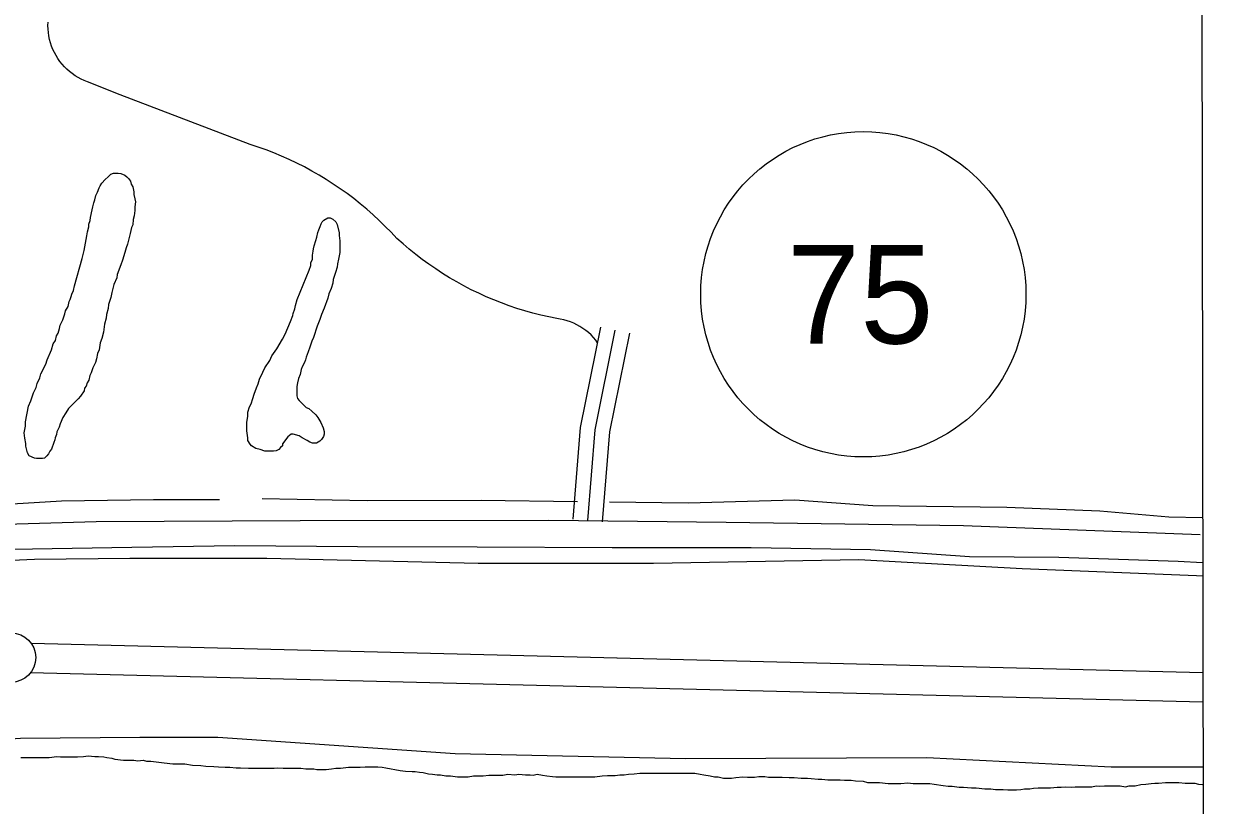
# Model space of a CAD drawing. Extents: x 3297772 to 3335630, y 634068 to 659439.
# Drawn here: x 3332239 to 3333452, y 650673 to 651465 of the extents above; entities that cross this region are included whole.
import ezdxf

# ---------------------------------------------------------------- set-up
doc = ezdxf.new("R2010")
doc.units = 0
for name, color, linetype in [('V-GRID-FRAM', 7, 'Continuous'), ('V-LEVE-TOET', 7, 'Continuous'), ('V-ROAD-CNTR', 7, 'Continuous'), ('V-ROAD-IDEN', 7, 'Continuous'), ('V-SITE-VEGE', 7, 'Continuous'), ('V-SURV-LINE', 7, 'Continuous'), ('V-TOPO-SHOR', 7, 'Continuous')]:
    doc.layers.add(name, color=color, linetype=linetype)

msp = doc.modelspace()

# ---------------------------------------------------------------- linework, layer by layer
at = {"layer": 'V-GRID-FRAM'}
msp.add_lwpolyline([(3301870.2, 657630.6), (3333425.5, 657662.7), (3333452, 639478.7), (3301880.8, 639446.5), (3301870.2, 657630.6)], dxfattribs=at)
at = {"layer": 'V-LEVE-TOET'}
for points in [[(3329935.1, 650681.5), (3330160.7, 650698.7), (3330335.6, 650710.8), (3330546, 650738.2), (3330678.2, 650757.4), (3330832.7, 650781.8), (3330990.3, 650805.1), (3331122.4, 650823.4), (3331283, 650842.6), (3331453.8, 650854.8), (3331601.2, 650866.9), (3331733.4, 650883.1), (3331859.4, 650896.3), (3331986.5, 650908.4), (3332089.2, 650915.5), (3332249.8, 650922.6), (3332346.4, 650923.6), (3332485.6, 650923.5), (3332700.1, 650918.3), (3332878, 650918.3), (3333086.4, 650922.3), (3333252.1, 650913.1), (3333429, 650905.9), (3333435.4, 650905.5)], [(3333435.6, 650711.6), (3333434, 650711.7), (3333342.5, 650711.7), (3333155.5, 650721), (3332910.5, 650720), (3332676.7, 650725.2), (3332435.8, 650741.6), (3332356.5, 650741.6), (3332235.5, 650740.6), (3332099.3, 650731.5), (3331851.2, 650711.3), (3331608.3, 650690), (3331357.2, 650671.8), (3331163, 650652.6), (3331004.4, 650628.2), (3330896.7, 650612), (3330716.7, 650578.5), (3330574.4, 650555.2), (3330476.8, 650542), (3330268.4, 650518.7), (3330075.3, 650499.5), (3329982.8, 650488.3)]]:
    msp.add_lwpolyline(points, dxfattribs=at)
at = {"layer": 'V-ROAD-CNTR'}
for points in [[(3332288, 651415), (3332285.2, 651417.2), (3332282.6, 651419.5), (3332280.1, 651422), (3332277.7, 651424.6), (3332275.5, 651427.4), (3332273.5, 651430.3), (3332271.6, 651433.3), (3332269.9, 651436.4), (3332268.4, 651439.6), (3332267.1, 651442.9), (3332266, 651446.3), (3332265.1, 651449.7), (3332264.4, 651453.2), (3332263.8, 651456.7), (3332263.5, 651460.2), (3332263.4, 651463.7), (3332263.5, 651467.3)], [(3332656.9, 651216.9), (3332650, 651221.6), (3332643.3, 651226.5), (3332636.6, 651231.6), (3332630.1, 651236.9), (3332623.8, 651242.3), (3332617.5, 651247.8), (3332611.7, 651254.1), (3332605.7, 651260.1), (3332599.6, 651266.1), (3332593.4, 651271.8), (3332586.9, 651277.4), (3332580.4, 651282.9), (3332573.7, 651288.2), (3332566.9, 651293.3), (3332560, 651298.2), (3332552.9, 651303), (3332545.8, 651307.6), (3332538.5, 651312), (3332531.1, 651316.2), (3332523.6, 651320.3), (3332516, 651324.1), (3332508.3, 651327.8), (3332500.5, 651331.3), (3332492.7, 651334.6), (3332484.7, 651337.6), (3332476.7, 651340.5), (3332468.7, 651343.2), (3332336.6, 651393.6), (3332303.5, 651406.6), (3332300.2, 651407.9), (3332297, 651409.4), (3332293.9, 651411.1), (3332290.9, 651412.9), (3332288, 651415)], [(3332821.2, 651142.1), (3332819.3, 651144.6), (3332817, 651147.3), (3332814.6, 651149.9), (3332812, 651152.3), (3332809.2, 651154.5), (3332806.3, 651156.6), (3332803.3, 651158.6), (3332800.2, 651160.3), (3332797, 651161.8), (3332793.7, 651163.2), (3332790.4, 651164.3), (3332786.9, 651165.3), (3332783.4, 651166), (3332779.9, 651166.6), (3332771.7, 651168.2), (3332763.6, 651170.1), (3332755.5, 651172.1), (3332747.4, 651174.4), (3332739.4, 651176.9), (3332731.5, 651179.5), (3332723.7, 651182.4), (3332715.9, 651185.5), (3332708.2, 651188.7), (3332700.6, 651192.2), (3332693, 651195.8), (3332685.6, 651199.7), (3332678.3, 651203.7), (3332671, 651207.9), (3332663.9, 651212.3), (3332656.9, 651216.9)], [(3332796.3, 650963), (3332804, 651055.9), (3332824.4, 651157.7)], [(3332811.2, 650961.7), (3332818.9, 651053.8), (3332839.1, 651154.7)], [(3332826.1, 650960.5), (3332833.8, 651051.7), (3332853.8, 651151.8)], [(3329966, 650728.3), (3330358.9, 650756.1), (3330604, 650788.3), (3330853.6, 650826.4), (3331016.6, 650849.1), (3331146.5, 650864.5), (3331250.8, 650874), (3331392.6, 650887.9), (3331650.9, 650915.1), (3331869.6, 650937.5), (3332004, 650949.5), (3332127.9, 650955.3), (3332312.3, 650960.6), (3332519.4, 650961.7), (3332771.6, 650962.2), (3332951.8, 650960.2), (3333192.7, 650956.6), (3333432.9, 650947.5)]]:
    msp.add_lwpolyline(points, dxfattribs=at)
at = {"layer": 'V-ROAD-IDEN'}
msp.add_circle((3333090.9, 651191.2), 165, dxfattribs=at)
at = {"layer": 'V-SITE-VEGE'}
for points in [[(3332245.9, 651083), (3332248.6, 651091.1), (3332251.4, 651096.5), (3332252.4, 651100.8), (3332255.1, 651106.3), (3332256.2, 651110.6), (3332261.1, 651120.3), (3332262.7, 651124.7), (3332267.1, 651134.9), (3332268.7, 651140.9), (3332270.9, 651144.2), (3332271.9, 651149), (3332273.6, 651151.7), (3332275.2, 651156.6), (3332275.7, 651159.8), (3332278.5, 651165.3), (3332280.6, 651171.2), (3332281.2, 651174.5), (3332283.9, 651178.8), (3332285, 651183.7), (3332286, 651185.8), (3332287.1, 651189.1), (3332287.7, 651191.2), (3332289.3, 651195), (3332290.4, 651199.9), (3332298, 651227.5), (3332300.1, 651235.6), (3332302.8, 651250.3), (3332303.4, 651254.6), (3332305, 651259.5), (3332305, 651262.2), (3332306.1, 651266), (3332306.6, 651269.2), (3332308.3, 651276.8), (3332308.8, 651280), (3332309.9, 651283.8), (3332311, 651287.1), (3332312.1, 651291.4), (3332313.7, 651294.7), (3332315.3, 651299), (3332316.4, 651301.2), (3332318, 651303.9), (3332321.3, 651307.7), (3332324.5, 651310.4), (3332327.2, 651313.1), (3332329.9, 651314.1), (3332334.8, 651314.1), (3332337.5, 651313.6), (3332341.3, 651312), (3332343.5, 651310.4), (3332345.1, 651308.7), (3332347.3, 651306), (3332347.8, 651302.8), (3332349.4, 651300.1), (3332350.5, 651295.2), (3332350.5, 651292.5), (3332351.6, 651288.1), (3332352.1, 651284.9), (3332351.6, 651280), (3332351.6, 651276.2), (3332351, 651270.8), (3332350, 651267), (3332349.4, 651261.6), (3332348.3, 651258.9), (3332346.7, 651253), (3332344, 651242.1), (3332342.9, 651238.3), (3332341.3, 651233.5), (3332339.1, 651225.9), (3332337.5, 651221), (3332333.7, 651211.3), (3332333.2, 651208), (3332330.4, 651201), (3332328.3, 651192.9), (3332327.2, 651188), (3332325, 651180.9), (3332324.5, 651176.6), (3332322.9, 651170.7), (3332322.3, 651166.9), (3332320.7, 651160.9), (3332319.6, 651152.8), (3332318, 651146.3), (3332316.3, 651142), (3332315.3, 651134.9), (3332313.6, 651131.1), (3332312.5, 651125.7), (3332311.5, 651121.9), (3332308.8, 651116.5), (3332307.1, 651111.6), (3332306, 651108.9), (3332305, 651104.1), (3332303.3, 651101.4), (3332302.2, 651098.1), (3332300.6, 651095.9), (3332300.1, 651093.2), (3332296.3, 651087.8), (3332294.1, 651085.1), (3332284.4, 651075.4), (3332281.7, 651071), (3332278.4, 651066.2), (3332275.7, 651059.7)], [(3332481.5, 651112.1), (3332483.6, 651116.5), (3332488.5, 651124), (3332490.7, 651128.9), (3332495.6, 651135.9), (3332501.5, 651145.7), (3332504.2, 651150.6), (3332509.7, 651163.6), (3332511.8, 651169.5), (3332512.4, 651171.7), (3332514, 651176.5), (3332514.5, 651179.8), (3332516.2, 651185.8), (3332528.6, 651215.5), (3332530.3, 651220.4), (3332530.3, 651223.1), (3332531.9, 651226.9), (3332531.9, 651230.7), (3332532.4, 651235), (3332533, 651237.2), (3332533.5, 651240.4), (3332535.1, 651245.8), (3332536.2, 651249.1), (3332537.3, 651254), (3332538.4, 651256.7), (3332539.5, 651259.9), (3332540.6, 651262.6), (3332541.6, 651264.8), (3332543.3, 651266.4), (3332547.6, 651268.6), (3332549.8, 651268.6), (3332552.5, 651267.5), (3332555.7, 651264.8), (3332556.8, 651262.1), (3332559, 651253.4), (3332559, 651250.7), (3332559.5, 651245.3), (3332559.5, 651233.4), (3332558.4, 651226.9), (3332557.3, 651222), (3332556.8, 651218.8), (3332555.2, 651213.4), (3332554.1, 651210.1), (3332553, 651206.3), (3332552.4, 651202.5), (3332550.8, 651197.1), (3332548.6, 651191.7), (3332547.6, 651187.4), (3332543.8, 651177.1), (3332541.1, 651170.6), (3332539.4, 651165.7), (3332536.7, 651158.7), (3332532.9, 651147.3), (3332531.3, 651143.5), (3332529.1, 651137.6), (3332527.5, 651132.7), (3332525.3, 651127.3), (3332524.8, 651124.6), (3332523.7, 651121.9), (3332521.5, 651117.5), (3332520.5, 651114.8), (3332519.4, 651109.9), (3332517.8, 651105.6), (3332516.7, 651101.3), (3332516.1, 651097.5), (3332516.1, 651088.3), (3332516.7, 651085.6), (3332518.3, 651083.4), (3332525.3, 651076.4), (3332528, 651075.3), (3332531.3, 651072.6), (3332535.1, 651068.8), (3332537.2, 651066.1), (3332540.5, 651061.2), (3332542.6, 651055.8), (3332543.7, 651052), (3332543.7, 651049.3), (3332543.2, 651047.1), (3332541, 651043.9), (3332539.4, 651042.3), (3332536.1, 651040.1), (3332531.8, 651040.1), (3332529.1, 651041.2), (3332526.4, 651042.8), (3332521.5, 651045.5), (3332518.3, 651047.7), (3332512.3, 651049.3), (3332510.2, 651049.3), (3332506.9, 651046.6), (3332501.5, 651039.6), (3332501.5, 651037.4), (3332499.3, 651035.8), (3332497.7, 651033.6), (3332495, 651032.5), (3332492.3, 651032), (3332483.6, 651032), (3332478.7, 651033.6), (3332474.4, 651034.7), (3332470.1, 651037.4), (3332468.5, 651039), (3332466.3, 651042.8)], [(3332466.3, 651042.8), (3332466.3, 651045.5), (3332465.2, 651052.6), (3332465.2, 651061.2), (3332466.3, 651067.7), (3332466.3, 651071.5), (3332467.9, 651076.9), (3332469.6, 651080.2), (3332471.2, 651085.6), (3332472.8, 651089.9), (3332475, 651096.4), (3332476.6, 651100.2), (3332478.2, 651105.1), (3332481.5, 651112.1)], [(3332275.7, 651059.7), (3332274.6, 651056.4), (3332272.5, 651051.6), (3332271.9, 651048.9), (3332270.8, 651045.6), (3332270.3, 651043.4), (3332269.2, 651040.7), (3332267, 651034.2), (3332265.4, 651032.1), (3332263.8, 651029.4), (3332262.2, 651027.2), (3332260, 651025), (3332257.8, 651024.5), (3332251.9, 651024.5), (3332249.7, 651025), (3332244.3, 651027.2), (3332242.7, 651030.5), (3332242.1, 651033.2), (3332241, 651037), (3332241, 651039.7), (3332240, 651045.1), (3332239.4, 651050.5), (3332240.5, 651057.5), (3332240.5, 651061.9), (3332243.8, 651077.6), (3332245.9, 651083)]]:
    msp.add_lwpolyline(points, dxfattribs=at)
at = {"layer": 'V-SURV-LINE'}
for points in [[(3332246.3, 650837.2), (3333435.5, 650807.6)], [(3333435.6, 650777.6), (3332245.5, 650807.2)]]:
    msp.add_lwpolyline(points, dxfattribs=at)
msp.add_circle((3332226, 650822.7), 25, dxfattribs=at)
at = {"layer": 'V-TOPO-SHOR'}
for points in [[(3331720.3, 650940.1), (3331812.4, 650948), (3331897.3, 650958.6), (3331993.5, 650966.5), (3332078.7, 650974.7), (3332176.5, 650975.7), (3332277.3, 650981.6), (3332370.4, 650982.9), (3332437.4, 650983.2)], [(3332480.8, 650983.9), (3332587.3, 650981.9), (3332703, 650982.5), (3332800.8, 650981.1)], [(3332833.3, 650980.8), (3332913.2, 650979.7), (3333021.3, 650982.7), (3333100.5, 650977), (3333236.4, 650975.3), (3333330.9, 650971.6), (3333400.9, 650965.6), (3333435.3, 650964.7)], [(3331480.9, 650872.2), (3331601, 650879.7), (3331700.5, 650892.4), (3331786.7, 650899.9), (3331872, 650908.7), (3331934.8, 650912.7), (3332028.9, 650923.3), (3332129.3, 650927.2), (3332227.4, 650932.5), (3332348.6, 650934.6), (3332452.9, 650936.4), (3332577.5, 650935.4), (3332699.1, 650935), (3332836.1, 650934.5), (3332977.2, 650934.4), (3333098.3, 650932.2), (3333198.6, 650925.1), (3333289.2, 650924.6), (3333410.4, 650920.6), (3333435.3, 650919)], [(3332236, 650721.3), (3332240.8, 650721.3), (3332244.6, 650721.3), (3332250.1, 650721.3), (3332255.5, 650721.3), (3332259.3, 650721.3), (3332264.7, 650721.3), (3332272.3, 650722.4), (3332276.1, 650721.9), (3332282.6, 650721.9), (3332286.4, 650721.9), (3332293.4, 650721.9), (3332299.4, 650722.4), (3332304.3, 650722.9), (3332310.8, 650722.4), (3332314.6, 650722.4), (3332320, 650721.9), (3332323.3, 650721.3), (3332328.2, 650720.8), (3332331.4, 650719.7), (3332340.1, 650718.6), (3332343.9, 650718.6), (3332350.4, 650718.6), (3332354.7, 650718), (3332360.1, 650718.6), (3332363.4, 650717.5), (3332367.7, 650717.5), (3332373.2, 650717), (3332381.3, 650715.9), (3332390, 650714.8), (3332393.8, 650714.8), (3332398.1, 650714.8), (3332402.4, 650714.8), (3332410, 650713.7), (3332418.7, 650713.1), (3332423.6, 650712.6), (3332431.7, 650712.1), (3332436.6, 650712), (3332443.1, 650711.5), (3332448, 650711.5), (3332454.5, 650711)], [(3332454.5, 650711), (3332458.8, 650711), (3332467, 650710.4), (3332472.4, 650710.4), (3332480, 650710.4), (3332486, 650710.4), (3332493, 650710.4), (3332496.3, 650710.9), (3332502.2, 650710.4), (3332506, 650710.4), (3332512, 650710.4), (3332516.9, 650710.4), (3332520.1, 650710.4), (3332525, 650709.8), (3332528.3, 650709.8), (3332533.1, 650709.8), (3332536.4, 650709.3), (3332541.8, 650709.3), (3332545.6, 650709.3), (3332551, 650709.8), (3332555.4, 650710.4), (3332560.3, 650710.4), (3332568.4, 650711.5), (3332572.7, 650711.5), (3332580.3, 650711.5), (3332585.2, 650712), (3332591.2, 650712), (3332594.4, 650712), (3332598.2, 650712), (3332602.6, 650711.4), (3332606.4, 650710.9), (3332611.8, 650709.8), (3332615.6, 650709.3), (3332621, 650708.2), (3332626.4, 650707.6), (3332632.9, 650707.1), (3332636.2, 650707.1), (3332640.5, 650706.6), (3332644.3, 650706), (3332649.7, 650704.9), (3332653.5, 650704.4), (3332658.4, 650703.8), (3332661.7, 650703.8), (3332667.1, 650702.7), (3332672, 650702.7), (3332679, 650701.7), (3332684.4, 650701.7), (3332689.9, 650701.7), (3332695.3, 650702.7), (3332701.3, 650702.7), (3332705.1, 650702.7), (3332711, 650703.3), (3332715.9, 650703.3), (3332719.2, 650703.3), (3332725.1, 650703.3), (3332730, 650704.3), (3332737.1, 650703.8), (3332741.4, 650704.3), (3332747.9, 650703.8), (3332752.8, 650703.8), (3332756, 650703.3), (3332759.8, 650704.3), (3332765.3, 650703.3), (3332769.6, 650702.7), (3332775.6, 650702.2), (3332778.8, 650701.6), (3332782.6, 650701.6), (3332788, 650701.6), (3332791.8, 650701.6), (3332797.2, 650701.6), (3332801, 650701.6), (3332807, 650701.6), (3332810.8, 650701.6), (3332818.4, 650701.6), (3332826, 650702.7), (3332831.4, 650703.2), (3332839, 650703.2), (3332843.9, 650703.8), (3332848.2, 650703.8), (3332852.6, 650704.3), (3332858.5, 650704.8), (3332864, 650705.4), (3332871.5, 650705.4), (3332880.2, 650705.4), (3332884, 650705.4), (3332890.5, 650705.4), (3332895.4, 650705.4), (3332901.9, 650705.4), (3332906.3, 650705.4), (3332912.2, 650705.4), (3332916.6, 650705.4), (3332919.8, 650705.4), (3332925.2, 650704.3), (3332929, 650703.7), (3332935.5, 650702.6), (3332939.9, 650701.6), (3332943.7, 650701.6), (3332949.1, 650700.5), (3332957.2, 650700.5), (3332961.6, 650701), (3332968.6, 650701.6)], [(3332968.6, 650701.6), (3332973.5, 650701.5), (3332980.5, 650701.5), (3332984.9, 650702.1), (3332990.9, 650702.1), (3332994.6, 650701.5), (3332998.4, 650701.5), (3333003.9, 650701.5), (3333008.7, 650701.5), (3333015.8, 650701), (3333020.7, 650701), (3333027.7, 650700.4), (3333034.2, 650700.4), (3333038, 650699.9), (3333045.1, 650699.4), (3333048.9, 650699.4), (3333054.8, 650698.8), (3333058.1, 650698.8), (3333061.9, 650698.8), (3333067.3, 650698.8), (3333071.7, 650698.3), (3333078.7, 650698.3), (3333083, 650697.7), (3333090.6, 650697.2), (3333095, 650696.1), (3333102.6, 650696.1), (3333107.4, 650696.1), (3333116.1, 650695), (3333121.5, 650695), (3333129.1, 650695), (3333136.2, 650695.5), (3333141.6, 650695), (3333145.9, 650695), (3333151.4, 650695), (3333158.4, 650695), (3333162.8, 650694.4), (3333172, 650692.8), (3333176.9, 650692.3), (3333181.2, 650692.3), (3333188.2, 650691.2), (3333192.6, 650691.2), (3333200.7, 650690.6), (3333205.6, 650690.6), (3333214.3, 650689.5), (3333220.2, 650689.5), (3333225.1, 650689), (3333232.7, 650689), (3333237.6, 650688.4), (3333243.6, 650688.4), (3333246.3, 650688.4), (3333250.6, 650689), (3333254.4, 650689.5), (3333259.8, 650689.5), (3333263.6, 650690.1), (3333268.5, 650690.6), (3333272.8, 650690.6), (3333276.1, 650690.6), (3333281, 650690.6), (3333287.5, 650691.1), (3333291.8, 650691.1), (3333295.6, 650691.7), (3333302.1, 650691.1), (3333305.9, 650691.7), (3333310.8, 650691.7), (3333314.6, 650691.7), (3333319.5, 650691.7), (3333322.7, 650691.7), (3333327.1, 650692.7), (3333330.3, 650692.2), (3333335.8, 650692.7), (3333341.2, 650692.7), (3333347.7, 650692.7), (3333351.5, 650692.7), (3333356.9, 650691.6), (3333360.7, 650692.7), (3333366.7, 650692.7), (3333372.6, 650693.8), (3333377.5, 650694.4), (3333382.9, 650694.9), (3333386.7, 650695.4), (3333390.5, 650695.4), (3333397.6, 650696), (3333402.5, 650696), (3333405.7, 650696), (3333411.1, 650696), (3333417.6, 650695.4), (3333424.2, 650695.4), (3333427.4, 650695.4), (3333431.2, 650694.3), (3333435, 650693.8), (3333435.7, 650693.7)]]:
    msp.add_lwpolyline(points, dxfattribs=at)

# ---------------------------------------------------------------- texts
at = {"layer": 'V-ROAD-IDEN'}
msp.add_text('75', height=100, rotation=0.0733, dxfattribs=at).set_placement((3333013.4, 651141.1))

doc.saveas('drawing.dxf')
